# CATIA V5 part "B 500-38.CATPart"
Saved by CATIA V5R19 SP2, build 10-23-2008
Part number: B 500-38
Bounding box of the stored display mesh (mm): x -18.951 to 18.951, y -18.952 to 18.952, z 0 to 126
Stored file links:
  C:\Users\Bora\Desktop\3D Katı model\B serisi\B 500\B 500-38.CATPart
  C:\Program Files\Dassault Systemes\B19\intel_a\reffiles\standard\MetricThickPitch.txt
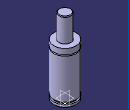
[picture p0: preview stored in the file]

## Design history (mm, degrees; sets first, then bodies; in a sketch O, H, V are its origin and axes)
Body1 (main body)
  Sketch1 on yz-plane, origin (0, 0, 0), H (0, 1, 0), V (0, 0, 1)
    point P3 (10, 125)
    point P5 (10, 125)
    point P7 (19, 76.5)
    point P8 (19, 74.5)
    point P12 (19, 74.5)
    point P13 (19, 76.5)
    line L1 (19, 0) -> (19, 4)
    line L2 (10, 125) -> (10, 86)
    arc A1 centre (9, 125) radius 1 from (10, 125) to (9, 126) ccw
    arc A2 centre (19, 75.5) radius 1 from (19, 76.5) to (19, 74.5) ccw
    line L3 (16.5, 7.5) -> (16.5, 4)
    line L4 (19, 7.5) -> (19, 74.5)
    line L5 (19, 76.5) -> (19, 86)
    line L6 (9, 126) -> (0, 126)
    point P15 (0, 126)
    line L7 (10, 86) -> (19, 86)
    line L8 (0, 0) -> (19, 0)
    line L9 (16.5, 7.5) -> (19, 7.5)
    line L10 (16.5, 4) -> (19, 4)
    coincidence: P15 V, P3 P5, P7 P13, P8 P12
    tangency: L6 A1
    horizontal: L7 H, L8 H, L9 H, L10 H
  Shaft1: profile Sketch1, axis Sketch1.V, angle 360
  Sketch2 on face of Shaft1 from Sketch1.L8, origin (0, 0, 0), H (1, 0, 0), V (0, -1, 0)
    point P1 (0, 0)
  Hole1: placed by Sketch2, at (0, 0, 0) direction (0, 0, 1), diameter 6.647, depth 7, threaded "M8", thread diameter 8, thread depth 7, pitch 1.25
